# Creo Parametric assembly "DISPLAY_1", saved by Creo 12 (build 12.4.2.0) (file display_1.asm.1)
Units: Custom; MM, KILOGRAM, SECS

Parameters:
  PTC_WM_ITERATION = "0"
  PTC_WM_VERSION = "-.0"
  PTC_WM_LIFECYCLE_STATE = "In Work"
  PTC_WM_LIFECYCLE = "MO_CADDocument"
  PTC_WM_CREATED_BY = "Maximilian Roepper (Z0017RMS: MO)"
  PTC_WM_CREATED_ON = "18-Sep-26 11:36:42 AM"
  PTC_WM_MODIFIED_BY = "Maximilian Roepper (Z0017RMS: MO)"
  PTC_WM_MODIFIED_ON = "18-Sep-26 11:36:46 AM"
  PDMLINKNUMBER = "PDM000071455324"
  PTC_WM_NUMBER = "PDM000071455324"

Other parameters: WEIGHT, WEIGHT_FACTOR, WEIGHT_ADD, MC_ERRORS, SUPPLIER

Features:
  1. coordinate system
  2. imported feature
  3. component "FRAME_1_2_3"
  4. component "METAL_BANDAGE_1"
  5. component "TFT_1"
  6. component "SCREEN_1"

Other named items: DRW_VIEW_ORG, ROUGH-GROB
